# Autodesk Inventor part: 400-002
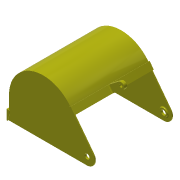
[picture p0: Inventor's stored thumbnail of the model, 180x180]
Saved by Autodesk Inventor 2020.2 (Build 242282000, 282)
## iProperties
Created: 2014-01
Part Number: 400-002
Material: Ogólny
Document SubType Name: Modeling
Designer: F.Stasiak
Density: 1 g/cm^3
Appearance: Żółta
Manager: www.cadconsulting.pl
Company: Fabian Stasiak CAD Consulting
Author: F.Stasiak
Subject: Zbiór ćwiczeń. Autodesk Inventor 2020. Kurs podstawowy
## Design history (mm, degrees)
sketch "Szkic1"
  geometry: L1 (0, -80)-(-800, -80); L2 (-800, -80)-(-800, 145); L3 (-171.636, 357.164)-(63.626, 48.495); A1 r 350 centre (-450, 145) between (-171.636, 357.164) and (-800, 145); A2 r 80 centre (0, 0) between (0, -80) and (63.626, 48.495); 1 further point
  constraints: 6 end point, 4 point on circle, 4 tangent, 2 centre point, 1 coincident, 1 horizontal, 1 perpendicular
  dimensions: "d0" = 800 distance from line of A2.centre L2; "d1" = 350 radius of A1; "d2" = 80 radius of A2; "d3" = 225 distance of L1.end L2.end
extrude "Wyciągnięcie proste1" new body sketch "Szkic1" stored distance "d4" = 800; taper "d5" = 0 deg
feature "Skorupa1" dims "d6" = 10
hole "Otwór1" diameter "d9" = 50; stored, may be unused: countersink angle "d13" = 90 deg, drill point angle "d15" = 118 deg; dims "d7" = 10, "d8" = 10, "d10" = 6, "d11" = 4, "d12" = 2, "d14" = 8
sketch "Szkic6"
  geometry: C1 r 25 at (790, 80) reference; C2 r 40 at (790, 80); A1 r 80 centre (790, 80) between (790, 0) and (853.626, 128.495) reference
  constraints: 1 centre point, 1 coincident
  dimensions: "d37" = 80 diameter of C2
extrude "Wyciągnięcie proste5" join sketch "Szkic6" distance "d38" = 10; taper "d39" = 0 deg
fillet "Zaokrąglenie2" dims "d40" = 10
sketch "Szkic7"
  geometry: C1 r 25 at (0, 80) reference; C2 r 40 at (0, 80); A1 r 80 centre (0, 80) between (-63.626, 128.495) and (0, 0) reference
  constraints: 1 centre point, 1 coincident
  dimensions: "d41" = 80 diameter of C2
extrude "Wyciągnięcie proste6" join sketch "Szkic7" distance "d42" = 10; taper "d43" = 0 deg
fillet "Zaokrąglenie3" dims "d44" = 10
sketch "Szkic3"
  geometry: L1 (-171.636, 357.164)-(-187.543, 345.04); L2 (-145.11, 289.367)-(-121.25, 307.553); L3 (-121.25, 307.553)-(-163.683, 363.226); L4 (-163.683, 363.226)-(-187.543, 345.04); L5 (-187.543, 345.04)-(-145.11, 289.367); 2 further points
  constraints: 10 end point, 3 parallel, 1 midpoint, 1 perpendicular
  dimensions: "d18" = 70 distance of L1.end L2.start; "d20" = 30 distance of L2.start L2.end; "d21" = 10 distance from line of L1.start L3
extrude "Wyciągnięcie proste2" join sketch "Szkic3" stored distance "d22" = 810; taper "d23" = 0 deg
sketch "Szkic4"
  geometry: L1 (-121.25, 307.553)-(-163.683, 363.226) reference; L2 (-163.683, 363.226)-(-60.291, 442.029); L3 (-17.858, 386.357)-(-121.25, 307.553); C1 r 15 at (-39.074, 414.193); A1 r 35 centre (-39.074, 414.193) between (-17.858, 386.357) and (-60.291, 442.029); 1 further point
  constraints: 4 end point, 2 centre point, 2 point on circle, 2 tangent, 1 coincident, 1 parallel, 1 perpendicular
  dimensions: "d24" = 130 distance of L3.start L1.start; "d25" = 30 diameter of C1
extrude "Wyciągnięcie proste3" join sketch "Szkic4" stored distance "d26" = 30; taper "d27" = 0 deg
fillet "Zaokrąglenie1" dims "d28" = 10
sketch "Szkic5"
  geometry: L1 (-800, -80)-(0, -80) reference; L2 (-790, 15)-(-820, 15); L3 (-820, 15)-(-820, -85); L4 (-820, -85)-(-790, -85); L5 (-790, -85)-(-790, 15); 2 further points
  constraints: 8 end point, 2 parallel, 1 horizontal, 1 perpendicular, 1 point on line
  dimensions: "d29" = 5 distance between parallel lines of L4 L1; "d30" = 30 distance of L3.end L4.end; "d31" = 100 distance of L2.end L3.end
extrude "Wyciągnięcie proste4" join sketch "Szkic5" stored distance "d32" = 810; taper "d33" = 0 deg
chamfer "Faza1" distance "d34" = 20; stored, may be unused: second distance "d35" = 70, angle "d36" = 45 deg
node "Bryła1"
